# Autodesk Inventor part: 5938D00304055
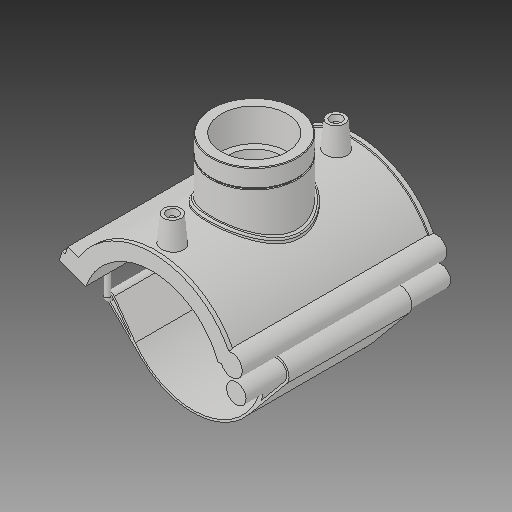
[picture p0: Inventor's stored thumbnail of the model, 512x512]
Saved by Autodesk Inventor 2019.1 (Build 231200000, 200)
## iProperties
Created: 2017-07
Part Number: 5938D00304055
Material: Generic
Description: PLASSON TRANSITION SADDLE 4''DIPS x 2"NPT
Document SubType Name: Modeling
Designer: KIM
Density: 1 g/cm^3
Appearance: Default
Author: KIM
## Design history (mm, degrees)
derived "5938D.ipt"
feature "Solid1::5938D.ipt"
tag "TaggingFeature1"
body "Solid1"
other parameters: "d_" = 121.3, "B_" = 165.1, "H_" = 46.736, "L_" = 176.022, "d_t" = 6, "G_" = 56.656, "d148" = 1.8195, "d160" = 1.8195, "d169" = 1.8195, "d192" = 4.852, "d0" = 121.3, "d1" = 145.56, "d2" = 412.75, "d3" = 30.325, "d4" = 176.022, "d5" = 0, "d40" = 75.6912, "d41" = 79.3184, "d43" = 0, "d45" = 0, "d47" = 119.516, "d48" = 73.6528, "d50" = 0, "d78" = 94.78, "d79" = 15, "d80" = 70.4088, "d82" = 5 deg, "d84" = 4, "d85" = 14, "d86" = 0, "d87" = 3, "d88" = 0, "d96" = 148.4712, "d97" = 3.52044, "d98" = 0, "d102" = 1.69968, "d103" = 56.656, "d104" = 28.0416, "d105" = 0, "d106" = 45.3248, "d108" = 0, "d109" = -15.57867, "d111" = 0.5, "d112" = 0.5, "d113" = 0, "d114" = 0.5, "d117" = 0.56656, "d120" = 140 deg, "d121" = 24.228, "d122" = 20 deg, "d123" = 582.24, "d124" = 87.336, "d126" = 0, "d143" = 124.939, "d145" = 18.66154, "d149" = 1.8195, "d150" = 20.52769, "d153" = 176.022, "d154" = 0, "d156" = 72.78, "d157" = 160 deg, "d159" = 4.852, "d161" = 1.8195, "d162" = 105.6132, "d163" = 0, "d164" = 60.65, "d167" = 12.13, "d168" = 71.00488, "d170" = 1.8195, "d172" = 0, "d173" = 1, "d175" = 60.65, "d176" = 20 deg, "d177" = 8.491, "d178" = 24.26, "d180" = 0, "d183" = 9.704, "d184" = 6.7928, "d185" = 57.20715, "d186" = 57.20715, "d187" = 72.78, "d188" = 7.278, "d189" = 8.491, "d190" = 0, "d191" = 87.336, "d193" = 4.852, "d194" = 2.48665, "d195" = 90 deg, "d197" = 0, "d199" = 0
